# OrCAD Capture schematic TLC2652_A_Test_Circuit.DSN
size A; title: TLC2652, TLC2652A, TLC2652Y Advanced LinCMOS PRECISION; rev: 1.1; note: Datasheet: SLOS019E EVM: N/A
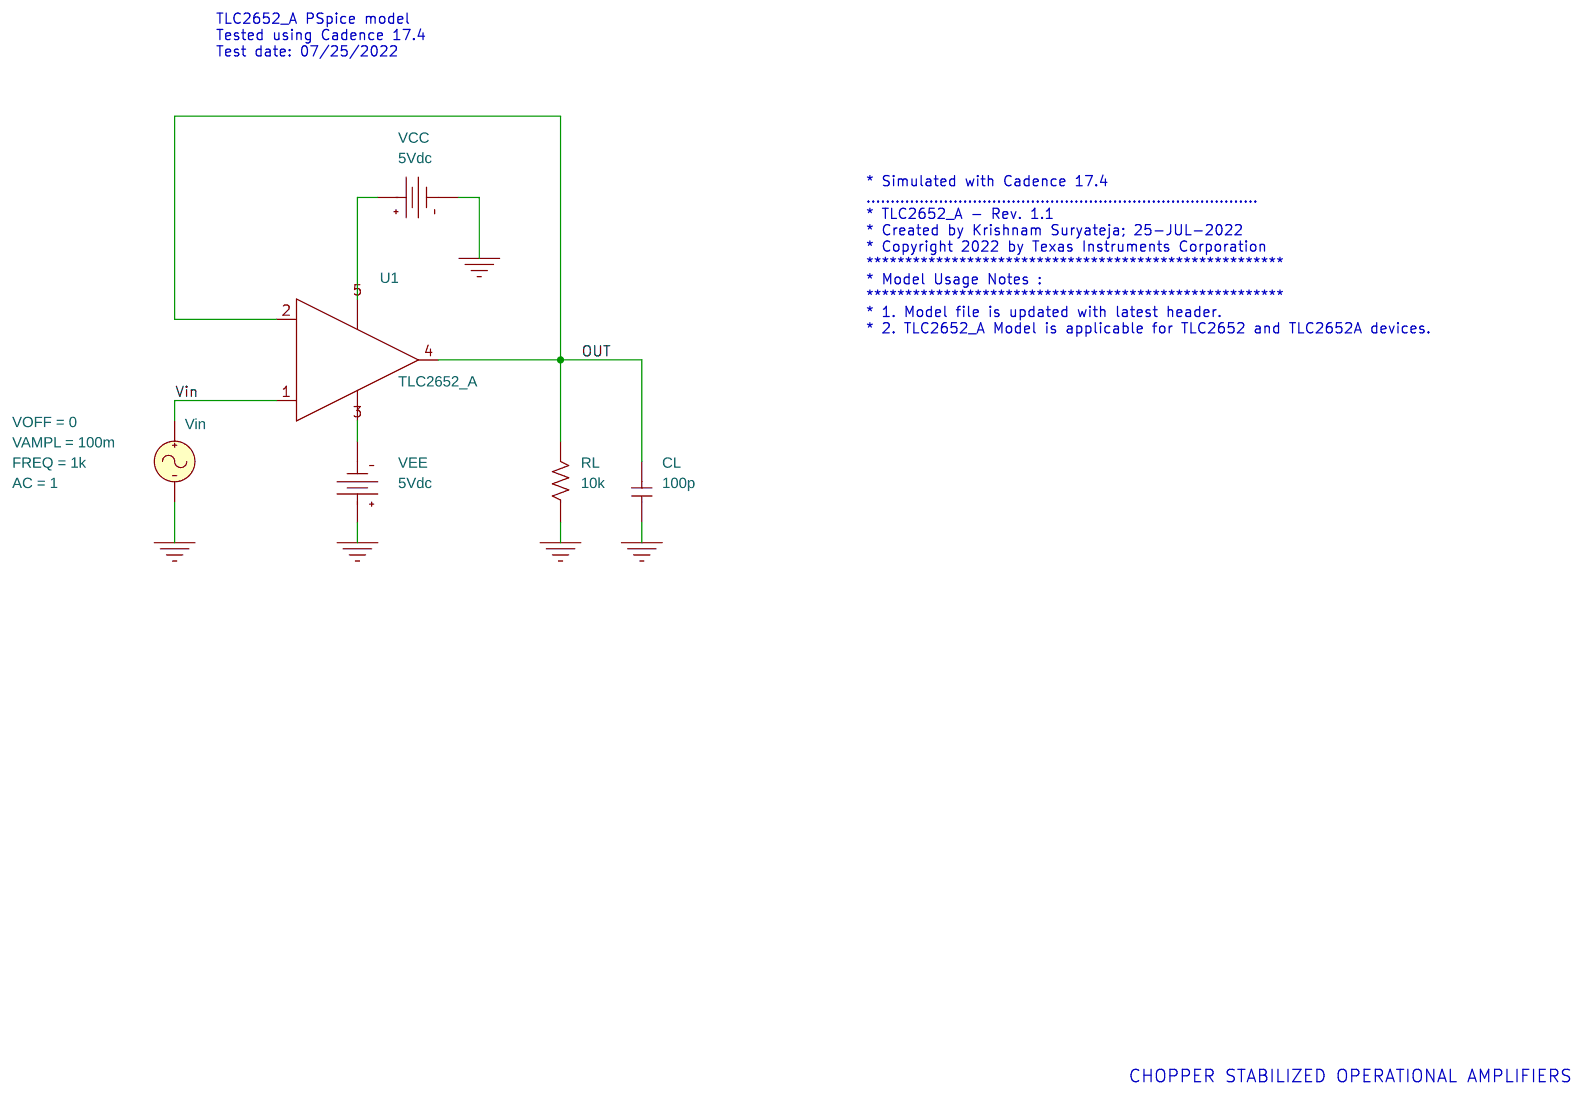
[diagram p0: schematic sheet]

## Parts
CL  100p  [RAD/CK05]
RL  10k  [AX/RC05]
U1  TLC2652_A
VCC  VDC
VEE  VDC
Vin  VSIN

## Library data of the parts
CL = C
RL = R
U1 = TLC2652_A
VCC VEE = VDC: DC: 5Vdc
Vin = VSIN: AC: 1; FREQ: 1k; VAMPL: 100m; VOFF: 0

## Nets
Vin: U1.1(+) Vin.1(+)
0: CL.1 RL.1 VCC.1(-) VEE.0(+) Vin.2(-)
OUT: CL.2 RL.2 U1.2(-) U1.4(OUT)
N22995: U1.5(V+) VCC.0(+)
N23017: U1.3(V-) VEE.1(-)

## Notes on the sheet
- TLC2652_A PSpice model
  Tested using Cadence 17.4
  Test date: 07/25/2022
- * Simulated with Cadence 17.4
  .................................................................................
  * TLC2652_A - Rev. 1.1
  * Created by Krishnam Suryateja; 25-JUL-2022
  * Copyright 2022 by Texas Instruments Corporation
  ******************************************************
  * Model Usage Notes :
  ******************************************************
  * 1. Model file is updated with latest header.
  * 2. TLC2652_A Model is applicable for TLC2652 and TLC2652A devices.
- CHOPPER STABILIZED OPERATIONAL AMPLIFIERS
